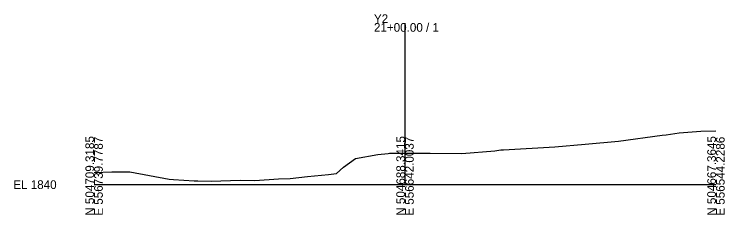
# Model space of a CAD drawing. Extents: x -26 to 203, y -10 to 3574.
# Drawn here: x -25.7 to 202.8, y 990.3 to 1054.8 of the extents above; entities that cross this region are included whole.
import ezdxf

# ---------------------------------------------------------------- set-up
doc = ezdxf.new("R2010")
doc.units = 0
doc.layers.add('Exist Cross Section Cell', color=7, linetype='Continuous')
doc.layers.add('Exist XS Ground Line', color=7, linetype='Continuous')

msp = doc.modelspace()

# ---------------------------------------------------------------- linework, layer by layer
at = {"layer": 'Exist Cross Section Cell'}
for p, q in [((100, 1000), (100, 1051.95)), ((0, 1000), (100, 1000)), ((100, 1000), (200, 1000))]:
    msp.add_line(p, q, dxfattribs=at)
at = {"layer": 'Exist XS Ground Line'}
for p, q in [((188.18, 1016.67), (195.09, 1017.21)), ((195.09, 1017.21), (200, 1017.32)), ((168.67, 1013.97), (182.68, 1015.92)), ((182.68, 1015.92), (184.02, 1016.05)), ((184.02, 1016.05), (188.18, 1016.67)), ((148.18, 1012.11), (157.97, 1013.03)), ((157.97, 1013.03), (168.67, 1013.97)), ((94.54, 1010.04), (94.96, 1010.14)), ((94.96, 1010.14), (100, 1010.12)), ((100, 1010.12), (103.38, 1010.11)), ((103.38, 1010.11), (105.13, 1010.13)), ((105.13, 1010.13), (106.24, 1010.12)), ((106.24, 1010.12), (106.63, 1010.12)), ((106.63, 1010.12), (108.07, 1010.13)), ((108.07, 1010.13), (118.24, 1009.98)), ((118.24, 1009.98), (128.84, 1010.9)), ((128.84, 1010.9), (130.76, 1011.17)), ((130.76, 1011.17), (131.33, 1011.22)), ((131.33, 1011.22), (131.72, 1011.24)), ((131.72, 1011.24), (148.18, 1012.11)), ((80.16, 1005.65), (84.02, 1008.45)), ((84.02, 1008.45), (91.25, 1009.67)), ((91.25, 1009.67), (94.54, 1010.04)), ((77.98, 1003.61), (80.16, 1005.65)), ((0, 1003.94), (5.75, 1004.15)), ((5.75, 1004.15), (11.52, 1004.08)), ((11.52, 1004.08), (24.17, 1001.79)), ((68.6, 1002.57), (75.34, 1003.27)), ((75.34, 1003.27), (77.98, 1003.61)), ((24.17, 1001.79), (25.58, 1001.68)), ((25.58, 1001.68), (32.14, 1001.27)), ((32.14, 1001.27), (33.31, 1001.24)), ((33.31, 1001.24), (37.69, 1001.1)), ((37.69, 1001.1), (47.02, 1001.43)), ((47.02, 1001.43), (51.72, 1001.34)), ((51.72, 1001.34), (59.28, 1001.83)), ((59.28, 1001.83), (63.1, 1002.01)), ((63.1, 1002.01), (68.6, 1002.57))]:
    msp.add_line(p, q, dxfattribs=at)

# ---------------------------------------------------------------- texts
at = {"layer": 'Exist Cross Section Cell'}
for s, p in [('Y2', (90, 1051.95)), ('21+00.00 / 1', (90, 1049.15)), ('EL 1840', (-26, 998.6))]:
    msp.add_text(s, height=2.8, dxfattribs=at).set_placement(p)
for s, p in [('N 504709.3185', (0, 990)), ('E 556739.7787', (2.8, 990)), ('N 504688.3415', (100, 990)), ('E 556642.0037', (102.8, 990)), ('N 504667.3645', (200, 990)), ('E 556544.2286', (202.8, 990))]:
    msp.add_text(s, height=2.8, rotation=90, dxfattribs=at).set_placement(p)

doc.saveas('drawing.dxf')
